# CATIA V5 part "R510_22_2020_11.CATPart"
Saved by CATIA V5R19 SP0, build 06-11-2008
Material "Steel": density 7860 kg/m3, Young's modulus 2e+11 Pa, Poisson ratio 0.266, thermal expansion 1.17e-05 1/K
Bounding box of the stored display mesh (mm): x -10 to 9.969, y -9.942 to 9.942, z 0 to 82
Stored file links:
  G:\Podręcznik\CD\Narzędzia\Arkusz Excel\Modele narzędzi\R510.22-2020-11.CATPart
  C:\Program Files\Dassault Systemes\B19\intel_a\startup\materials\Catalog.CATMaterial
  F:\OSTATNIE\DesignTable2.xls
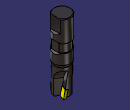
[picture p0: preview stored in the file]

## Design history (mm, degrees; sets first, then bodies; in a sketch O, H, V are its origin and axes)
Parameters
  CuttingType = "CUTTER"
  d = 20 mm {design table}
  D = 20 mm {design table}
  L = 82 mm {design table}
  l = 50 mm {design table}
  alfa = 11 deg {design table}
  gammap = 9 deg {design table}
  S = 3.18 mm {design table}
  epsilon = 85 deg {design table}
  lp = 10 mm {design table}
  x = 0.1131 mm {design table}
  gammaf = -12 deg {design table}
  z = 3 {design table}
  teta = 120 deg {design table}
  `lp'` = 9.8769 mm {design table}
  `lp''` = 5.8466 mm {design table}
Body1 "BODY" (main body), material "Steel"
  Sketch1 "sketch" on yz-plane, origin (0, 0, 0), H (0, 1, 0), V (0, 0, 1)
    line L1 (0, 1.3409) -> (9, 0.2358)
    line L2 (9, 0.2358) -> (9, 32)
    point P3 (9, 32)
    line L3 (9, 32) -> (9, 32)
    point P4 (10, 32)
    line L4 (10, 34.8284) -> (10, 47)
    point P5 (10, 47)
    line L5 (10, 47) -> (9, 47)
    line L6 (9, 47) -> (9, 57)
    line L7 (9, 57) -> (10, 57)
    point P8 (10, 57)
    line L8 (10, 57) -> (10, 81.2929)
    line L9 (10, 81.2929) -> (9.2929, 82)
    line L10 (9.2929, 82) -> (0, 82)
    point P11 (0, 82)
    line L11 (0, 82) -> (0, 1.3409)
    construction line L12 (0, -29.1199) -> (0, 199.3445)
    point P12 (0, -29.1199)
    construction line L13 (0, 0.1131) -> (10, 0.1131)
    point P14 (0, 0.1131)
    point P15 (10, 0.1131)
    construction line L14 (0, 1.3409) -> (10, 0.1131)
    axis line L15 (10, 0.1131) -> (10, -5.5625)
    line L16 (9, 32) -> (10, 34.8284)
    point P17 (9, 32)
    length L6 = 10 {= 0.2*l}
    distance P3 H = 32 {= L-l}
    length L9 = 1
    angle L8 L9 = 45
    distance L6 L8 = 1
    distance L8 L11 = 10 {= d/2}
    length L13 = 10 {= D/2}
    distance H L13 = 0.1131 {= x}
    distance L10 L7 = 25 {= 0.5*l}
    distance P15 L2 = 1
    distance P4 P5 = 15 {= 0.3*l}
    length L16 = 3 {= 0.2*(0.3*l)}
    angle L1 L2 = 83
    vertical: L2 V, L4 V, L6 V, L8 V, L11 V, L12 V, L15 V
    horizontal: L3 H, L5 H, L7 H, L10 H, L13 H
    coincidence: P8 L4, P11 V, P12 V, L1 L14, P14 L12, L3 P4, L4 P4, P3 P17
  Shaft1: profile Sketch1, axis Z axis, angle 360
  Fillet1: radius 1 {= 0.1*D/2}, on edge [face of Shaft1 from Sketch1.L1 | face of Shaft1 from Sketch1.L2]
  Sketch2 on zx-plane, origin (0, 0, 0), H (-1, 0, 0), V (0, 0, 1)
    line L1 (-8, 82) -> (-8, 67)
    line L2 (-8, 67) -> (-10, 65)
    line L3 (-10, 65) -> (-10, 59)
    line L4 (-10, 59) -> (-8, 57)
    point P5 (-8, 57)
    line L5 (-8, 57) -> (-8, 47)
    line L6 (-8, 47) -> (-10, 45)
    point P7 (-10, 45)
    line L7 (-10, 45) -> (-10, 45)
    line L8 (-10, 45) -> (-13, 45)
    line L9 (-13, 45) -> (-13, 82)
    line L10 (-13, 82) -> (-8, 82)
    reference projected line E1 through (0, 0) direction (0, 1) from axis of face of Shaft1 from Sketch1.L8
    reference projected line E2 (-9.2929, 82) -> (9.2929, 82) from edge [face of Shaft1 from Sketch1.L9 | face of Shaft1 from Sketch1.L10]
    distance L3 E1 = 10 {= d/2}
    distance L1 L3 = 2
    angle L2 L3 = 45
    angle L4 L3 = 45
    length L5 = 10 {= l*0.2}
    length L1 = 15 {= 0.3*l}
    distance P5 L10 = 25 {= 0.5*l}
    distance L9 L1 = 5
    distance L7 L5 = 2
    angle L5 L6 = 45
    vertical: L1 V, L3 V, L5 V, L7 V, L9 V
    horizontal: L8 H, L10 H
    coincidence: L10 E2, L1 L5, P7 L8
  Pocket1: profile Sketch2, direction (0, -1, 0), length 8, mirrored extent
  Plane1: type Angle, Angle 150, Direction Z axis, RefPlane yz-plane
  Plane2: type Offset, Offset 1, RefPlane Plane1, reversed
  Sketch3 "gammap_os_obrotu" on Plane2, origin (0.866, -0.5, 0), H (-0.5, -0.866, 0), V (0, 0, 1)
    line L1 (1.3076, 0) -> (-0.9434, 0)
    reference intersected line E1 through (0, 0) direction (-1, 0) from xy-plane
    horizontal: L1 H
    coincidence: E1 L1
  Plane3 "gammap": type Angle, Angle -9 {= -gammap}, Direction Sketch3, RefPlane Plane2
  Plane4: type Offset, Offset 0.5, RefPlane Plane3, reversed
  Sketch4 on Plane4, origin (1.2725, -0.7347, 0.2327), H (-0.5, -0.866, 0), V (-0.1355, 0.0782, 0.9877)
    line L1 (-10, -2.3223) -> (-10, 6.2448)
    distance V L1 = 10 {= D/2}
  Plane5 "gammaf": type Angle, Angle 12 {= -gammaf}, Direction Sketch4, RefPlane Plane4
  Plane6: type Offset, Offset 0.5, RefPlane Plane5
  Plane7: type Angle, Angle 90, Direction Sketch4, RefPlane Plane5
  Sketch5 on Plane7, origin (2.8716, 9.0198, -0.3577), H (0.9503, -0.3114, 0), V (0.0101, 0.0309, 0.9995)
    point P1 (3.6086, 0.3579)
    line L1 (3.6086, 0.3579) -> (0.3714, 0.4819)
    line L2 (0.3714, 0.4819) -> (-0.9703, 9.1423)
    line L3 (-0.9703, 9.1423) -> (2.0776, 10.24)
    line L4 (2.0776, 10.24) -> (3.6086, 0.3579)
    reference projected line E1 (3.9266, -1.6951) -> (2.6151, 6.7709) from Sketch4
    construction line L5 (2.0776, 10.24) -> (-2.825, 9.4805)
    axis line L6 (3.6086, 0.3579) -> (-0.0816, -0.2138)
    reference intersected line E2 through (-0.0001, 0.3579) direction (-1, 0) from xy-plane
    distance L2 L4 = 3.18 {= S}
    length L4 = 10 {= lp}
    angle L5 L3 = 11 {= alfa}
    angle L6 L1 = 11 {= alfa}
    coincidence: L4 E1, P1 E2
    perpendicularity: L5 L2
    parallelism: L6 L5
  Plane8: type Offset, Offset 10 {= D/2}, RefPlane Plane1, reversed
  Sketch6 on Plane8, origin (8.6603, -5, 0), H (-0.5, -0.866, 0), V (0, 0, 1)
    line L1 (-3.5247, -3) -> (-3.5247, 18.3474)
    arc A1 centre (-15.5247, 18.3474) radius 12 from (-3.5247, 18.3474) to (-10, 29) ccw
    point P4 (-10, 29)
    line L2 (-10, 29) -> (-10, -3)
    point P5 (-10, -3)
    line L3 (-10, -3) -> (-3.5247, -3)
    axis line L4 (-10, -3) -> (-3.5247, -2.4335)
    point P6 (-10, -3)
    point P7 (-3.5247, -2.4335)
    reference projected line E1 (-9, 32) -> (9, 32) from edge [face of Shaft1 from Sketch1.L2 | face of Shaft1 from Sketch1.L16]
    distance L2 V = 10 {= D/2}
    angle L4 L2 = 85 {= epsilon}
    distance E1 P4 = 3
    radius A1 = 12
    distance H L3 = 3
    length L4 = 6.5 {= 0.65*lp}
    vertical: L1 V, L2 V
    horizontal: L3 H
    tangency: L1 A1
    coincidence: P6 P5, P7 L1
  Pocket2: profile Sketch6, direction (-0.866, 0.5, 0), up to Plane6
  CircPattern1: of Pocket2, instances 3 {= z}, angular step 120 {= teta}, axis from Z axis
  Sketch7 on Plane5, origin (3.3239, -1.0481, 0.5894), H (-0.3066, -0.9518, 0), V (-0.1456, 0.0469, 0.9882)
    line L1 (-9.7669, 9.3981) -> (-3.8102, 10.1175)
    point P1 (-9.7669, 9.3981)
    reference projected point E1 (-9.7669, 9.3981) from vertex [element of Sketch5 | element of Sketch5]
    reference projected line E2 (-9.4279, -0.899) -> (-9.757, 9.0955) from Sketch5.L4
    length L1 = 6 {= 0.6*lp}
    angle E2 L1 = 85 {= epsilon}
    coincidence: P1 E1
  Slot1: profile Sketch5, centre curve Sketch7
  CircPattern2: of Slot1, instances 3 {= z}, angular step 120 {= teta}, axis from Z axis
Body2 "INSERTS"
  Sketch8 "CUT" on yz-plane, origin (0, 0, 0), H (0, 1, 0), V (0, 0, 1)
    line L1 (4.1757, 0.5096) -> (10, 0)
    point P2 (10, 0)
    line L2 (10, 0) -> (10, 9.8769)
    line L3 (10, 9.8769) -> (4.1757, 10.3864)
    line L4 (4.1757, 10.3864) -> (4.1757, 0.5096)
    angle L3 L4 = 85
    length L2 = 9.8769 {= `lp'`}
    length L1 = 5.8466 {= `lp''`}
    distance L2 V = 10 {= D/2}
    vertical: L2 V, L4 V
    parallelism: L3 L1
    coincidence: P2 H
  Sketch9 "NOCUT" on yz-plane, origin (0, 0, 0), H (0, 1, 0), V (0, 0, 1)
    axis line L1 (10, 0) -> (0, 0.8749)
    point P1 (0, 0.8749)
    point P2 (10, 0)
    reference projected line E1 (4.0228, 0.5229) -> (10, 0) from Sketch8.L1
    reference projected point E2 (10, 0) from vertex [element of Sketch8 | element of Sketch8]
    line L2 (0, 0.8749) -> (4.1757, 0.5096)
    point P3 (4.1757, 0.5096)
    line L3 (4.1757, 0.5096) -> (4.1757, 10.3864)
    line L4 (4.1757, 10.3864) -> (9, 9.9644)
    line L5 (9, 9.9644) -> (9, 32)
    line L6 (9, 32) -> (10, 32)
    line L7 (10, 32) -> (10, 47)
    line L8 (10, 47) -> (9, 47)
    line L9 (9, 47) -> (9, 57)
    line L10 (9, 57) -> (10, 57)
    point P11 (10, 57)
    line L11 (10, 57) -> (10, 81.2929)
    point P12 (10, 82)
    line L12 (9.2929, 82) -> (0, 82)
    point P13 (0, 82)
    line L13 (0, 82) -> (0, 0.8749)
    line L14 (10, 81.2929) -> (9.2929, 82)
    length L9 = 10 {= 0.2*l}
    length L7 = 15 {= 0.3*l}
    distance L6 H = 32 {= L-l}
    distance L11 L13 = 10 {= d/2}
    distance L9 L11 = 1
    distance P3 P2 = 5.8466 {= `lp''`}
    distance L9 L7 = 1
    distance L5 P2 = 1
    length L3 = 9.8769 {= `lp'`}
    angle L10 L9 = 90
    distance P11 P12 = 25 {= 0.5*l}
    angle L11 L14 = 45
    length L14 = 1
    coincidence: P1 V, L1 E1, P2 E2, P13 V, L11 P12, L12 P12
    parallelism: L2 L1, L4 L1
    vertical: L3 V, L5 V, L7 V, L9 V, L11 V, L13 V
    horizontal: L6 H, L8 H, L12 H
  Sketch10 on Plane7, origin (2.8716, 9.0198, -0.3577), H (0.9503, -0.3114, 0), V (0.0101, 0.0309, 0.9995)
    point P1 (3.6086, 0.3579)
    line L1 (3.6086, 0.3579) -> (0.3714, 0.4819)
    line L2 (0.3714, 0.4819) -> (-0.9703, 9.1423)
    line L3 (-0.9703, 9.1423) -> (2.0776, 10.24)
    line L4 (2.0776, 10.24) -> (3.6086, 0.3579)
    reference intersected line E1 through (3.5711, 0.5998) direction (0.1531, -0.9882) from Plane5
    reference intersected line E2 through (-0.0001, 0.3579) direction (-1, 0) from xy-plane
    construction line L5 (2.0776, 10.24) -> (-8.7731, 8.559)
    axis line L6 (3.6086, 0.3579) -> (-3.0022, -0.6663)
    distance L2 L4 = 3.18 {= S}
    length L4 = 10 {= lp}
    angle L3 L5 = 11 {= alfa}
    angle L6 L1 = 11 {= alfa}
    coincidence: L4 E1, E2 P1
    perpendicularity: L5 L2
    parallelism: L6 L5
  Sketch11 on Plane5, origin (3.3239, -1.0481, 0.5894), H (-0.3066, -0.9518, 0), V (-0.1456, 0.0469, 0.9882)
    line L1 (-9.7669, 9.3981) -> (-3.8102, 10.1175)
    point P1 (-9.7669, 9.3981)
    reference projected point E1 (-9.7669, 9.3981) from vertex [element of Sketch10 | element of Sketch10]
    reference projected line E2 (-9.4381, -0.5873) -> (-9.7673, 9.4073) from Sketch10.L4
    angle L1 E2 = 85 {= epsilon}
    length L1 = 6 {= 0.6*lp}
    coincidence: P1 E1
  Rib1: profile Sketch10, centre curve Sketch11
  CircPattern3: of the body so far, instances 3 {= z}, angular step 120 {= teta}, axis from Z axis
  Sketch12 on face of Rib1, origin (0.0796, 0.1331, 1.2424), H (0.8083, -0.5887, 0), V (-0.5842, -0.8021, 0.1239)
    point P1 (0.4549, -10.026)
    line L1 (0.4549, -10.026) -> (-2.4414, -8.4217)
    line L2 (-2.4414, -8.4217) -> (-2.6264, -9.0259)
    point P3 (-2.6264, -9.0259)
    line L3 (-2.6264, -9.0259) -> (0.4549, -10.026)
    reference projected point E1 (0.4549, -10.026) from vertex [face of Rib1 | face of Rib1 | face of Rib1]
    reference projected line E2 (-2.6666, -9.0128) -> (0.4147, -10.0129) from edge [face of Rib1 | face of Rib1]
    reference projected point E3 (-2.6264, -9.0259) from vertex [face of Rib1 | face of Rib1 | face of Rib1]
    reference projected line E4 (-2.629, -9.0344) -> (-0.8719, -3.2974) from edge [face of Rib1 | face of Rib1]
    angle L1 L3 = 11
    coincidence: E1 P1, L3 E2, P3 E3, L2 E4
  Pocket3: profile Sketch12, direction along edge [face of Rib1 | face of Rib1], length 10 {= lp}
  CircPattern4: of Pocket3, instances 3 {= z}, angular step 120 {= teta}, axis from Z axis
Relations
  design table, configuration 1, drives d, D, L, l, alfa, gammap, S, epsilon, lp, x, gammaf, z, teta, `lp'`, `lp''`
